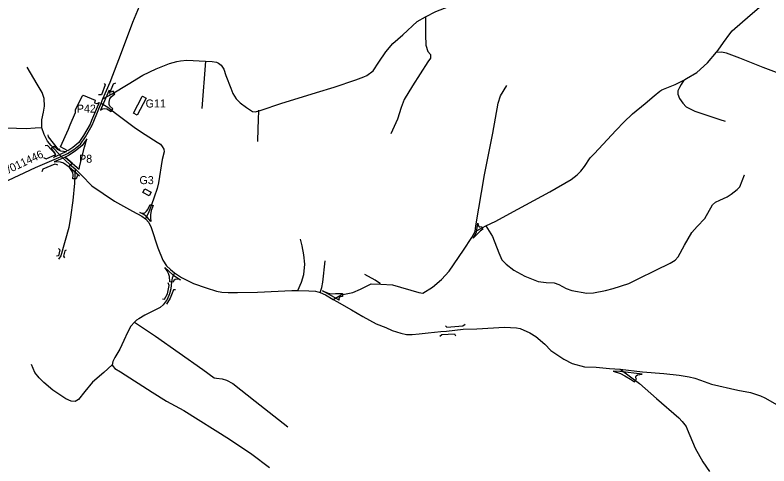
# Model space of a CAD drawing. Extents: x -439169 to -431590, y -1130011 to -1121081.
# Drawn here: x -437746 to -436804, y -1124342 to -1123779 of the extents above; entities that cross this region are included whole.
import ezdxf

# ---------------------------------------------------------------- set-up
doc = ezdxf.new("R2010")
doc.units = 0
for name, color, linetype in [('11811012_místní  komunikace_Stav', 7, 'Continuous'), ('11850012_silnice III třídy_Stav', 7, 'Continuous'), ('11850013_silnice III třídy_Stav', 7, 'Continuous'), ('11900012_účelová komunikace_Stav', 7, 'Continuous'), ('11930011_silniční most _ estakáda_Stav', 7, 'Continuous'), ('12060011_hromadná a parkovací garáž_Stav', 7, 'Continuous'), ('12060021_hromadná a parkovací garáž_Návrh', 7, 'Continuous'), ('12080011_parkoviště mimo prostor komunikace_Stav', 7, 'Continuous'), ('12080013_parkoviště mimo prostor komunikace_Stav', 7, 'Continuous')]:
    doc.layers.add(name, color=color, linetype=linetype)

msp = doc.modelspace()

# ---------------------------------------------------------------- linework, layer by layer
at = {"layer": '11811012_místní  komunikace_Stav'}
for points in [[(-437171.12, -1124049.48), (-437162.19, -1124044.79), (-437157.47, -1124042.33), (-437145.14, -1124036.37), (-437127.63, -1124026.96), (-437077.74, -1123999.89), (-437051.01, -1123984.4), (-437043.64, -1123978.68), (-437039.03, -1123973.89), (-437034.61, -1123967.99), (-437027.46, -1123957.15), (-437022.48, -1123952.17), (-436995.02, -1123922.48), (-436985.47, -1123912.78), (-436974.42, -1123902.09), (-436958.56, -1123889.36), (-436947.32, -1123879.96), (-436940.5, -1123874.06), (-436937.74, -1123872.4), (-436921.19, -1123865.6), (-436910.32, -1123860.06), (-436906.81, -1123858.22), (-436893.91, -1123850.48), (-436880.67, -1123838.52), (-436869.43, -1123825.25), (-436867.4, -1123822.67), (-436860.76, -1123813.08), (-436853.05, -1123802.26), (-436850.1, -1123798.39), (-436827.24, -1123778.84), (-436813.24, -1123766.85)], [(-437636.08, -1123883.43), (-437624.47, -1123877.16), (-437604.42, -1123865.04), (-437586.04, -1123853.98), (-437569.36, -1123846), (-437552.91, -1123839.49), (-437543.79, -1123836.77), (-437539.3, -1123835.94), (-437531.37, -1123835.35), (-437508.06, -1123836.58), (-437499.53, -1123836.99), (-437494.26, -1123837.72), (-437491.43, -1123838.91), (-437488.23, -1123841.38), (-437485.03, -1123846.32), (-437482.47, -1123854.55), (-437476.21, -1123870), (-437473.87, -1123876.86), (-437469.59, -1123883.52), (-437464.5, -1123888.37), (-437456.69, -1123894.29), (-437449.15, -1123899.27), (-437445.22, -1123899.82), (-437438.22, -1123897.84), (-437413.72, -1123889.36), (-437369.33, -1123875.54), (-437347.07, -1123868.9), (-437319.98, -1123859.87), (-437310.02, -1123855.81), (-437306.34, -1123854.15)], [(-437688.21, -1123955.73), (-437700.88, -1123941.89), (-437705.3, -1123936.47), (-437709.54, -1123927.99), (-437712.3, -1123919.69), (-437712.48, -1123909.6), (-437710.26, -1123900.01), (-437708.97, -1123892.64), (-437709.53, -1123883.23), (-437711.74, -1123875.67), (-437718, -1123864.98), (-437730.53, -1123843.82)], [(-437348.32, -1124134.23), (-437338.57, -1124128.5), (-437324.01, -1124125.78), (-437314.07, -1124121.28), (-437301.05, -1124114.77), (-437288.94, -1124115.39), (-437274.07, -1124116.08), (-437241.41, -1124125.78), (-437236.44, -1124126.37), (-437224.48, -1124119.04), (-437213.12, -1124109.45), (-437203.65, -1124099.05), (-437185.47, -1124072.77), (-437175.16, -1124056.77), (-437171.12, -1124049.48), (-437170.2, -1124042.28), (-437159.23, -1123978.37), (-437149.01, -1123926.54), (-437142.38, -1123888.8), (-437139.24, -1123879.95), (-437131.32, -1123866.86)], [(-437638.31, -1123889.08), (-437629.81, -1123894), (-437620.48, -1123901.62), (-437595.36, -1123920.11), (-437583.44, -1123928.26), (-437568.44, -1123937.51), (-437564.29, -1123940.21), (-437561.92, -1123942.95), (-437559.91, -1123946.61), (-437559.42, -1123949.57), (-437561.82, -1123959.52), (-437566.79, -1123988.6), (-437568.26, -1123995.43), (-437571.8, -1124006.63), (-437575.18, -1124016.15), (-437578.47, -1124024.65), (-437582.79, -1124033.49)], [(-437688.21, -1123955.73), (-437683.39, -1123960.36), (-437677.33, -1123965.51), (-437670.85, -1123971.05), (-437662.97, -1123979.06), (-437649.8, -1123992.14), (-437621.4, -1124011.29), (-437599.28, -1124024.01), (-437587.23, -1124030.39), (-437582.79, -1124033.49), (-437578.62, -1124038.31), (-437575.78, -1124044.37), (-437567.31, -1124069.59), (-437561.23, -1124085.08), (-437556.44, -1124092.28), (-437551.65, -1124096.7), (-437546.67, -1124101.13), (-437537.67, -1124106.97), (-437522.92, -1124114.35), (-437507.25, -1124119.69), (-437494.05, -1124124.08), (-437487.6, -1124125), (-437479.49, -1124125.56), (-437468.06, -1124125.56), (-437442.8, -1124125), (-437399.89, -1124123.16), (-437392.37, -1124123), (-437378.69, -1124123.34), (-437370.26, -1124124.08), (-437364.73, -1124125.56), (-437358.09, -1124128.69), (-437348.32, -1124134.23), (-437343.72, -1124136.7), (-437325.28, -1124147.13), (-437311.32, -1124155.58), (-437294.73, -1124164.8), (-437282.75, -1124169.41), (-437274.82, -1124173.1), (-437263.82, -1124176.59), (-437256.62, -1124178.06), (-437249.61, -1124178.06), (-437240.97, -1124177.14), (-437229.71, -1124176.03), (-437213.85, -1124174.19), (-437206.67, -1124173.82), (-437196.21, -1124172.53), (-437185.89, -1124171.42), (-437168.93, -1124170.87), (-437134.3, -1124168.86), (-437119.15, -1124169.81), (-437114.89, -1124170.75), (-437102.58, -1124176.2), (-437095.24, -1124180.7), (-437084.01, -1124190.23), (-437076.31, -1124197.98), (-437070.33, -1124202.35), (-437060.15, -1124208.92), (-437049.74, -1124214.37), (-437034.59, -1124218.63), (-437019.95, -1124218.75), (-437003, -1124220.41), (-436989.94, -1124221.51), (-436961.91, -1124224.61)], [(-437670.85, -1123971.05), (-437671.69, -1123988.91), (-437673.72, -1124010.67), (-437676.67, -1124031.32), (-437678.51, -1124044.23), (-437688.46, -1124079.59), (-437691.58, -1124084.14)], [(-437546.67, -1124101.13), (-437549.51, -1124107.62), (-437550.43, -1124112.41), (-437551.12, -1124121.03), (-437552.78, -1124127.11), (-437555.92, -1124134.49), (-437560.94, -1124140.9), (-437564.53, -1124144.22), (-437574.51, -1124149.25), (-437583.56, -1124153.82), (-437591.17, -1124158.33), (-437594.01, -1124160.26), (-437596.41, -1124162.84), (-437601.12, -1124167.87), (-437605.36, -1124175.62), (-437609.95, -1124185.41), (-437614.72, -1124196.42), (-437621.17, -1124206.94), (-437623.55, -1124211.85), (-437624.49, -1124215.97), (-437623.29, -1124218.11), (-437621.27, -1124220.51), (-437614.17, -1124224.64), (-437574.64, -1124250.28), (-437556.78, -1124261.32), (-437534.74, -1124273.15), (-437477.89, -1124309.12), (-437450.19, -1124327.53), (-437428.12, -1124344.34)], [(-436989.94, -1124221.51), (-436965.77, -1124239.3), (-436944.39, -1124257.92), (-436916.74, -1124282.08), (-436912.31, -1124286.88), (-436907.56, -1124293.26), (-436906.27, -1124296.4), (-436896.14, -1124320.18), (-436886.55, -1124337.33), (-436878.07, -1124349.51)], [(-436961.91, -1124224.61), (-436935.18, -1124226.92), (-436915.95, -1124229.12), (-436903.51, -1124231.15), (-436896.6, -1124232.63), (-436889.41, -1124235.03), (-436875.76, -1124240.4), (-436842.73, -1124247.63), (-436827.15, -1124250.77), (-436814.66, -1124254.63), (-436809.22, -1124257.21), (-436793.73, -1124265.97)]]:
    msp.add_lwpolyline(points, dxfattribs=at)
for points in [[(-437638.91, -1123897.76), (-437636.29, -1123896.06), (-437633.91, -1123895.45), (-437631.04, -1123895.93), (-437625.86, -1123899.16), (-437623.59, -1123895.86), (-437627.27, -1123892.58), (-437628.12, -1123890.63), (-437628.42, -1123887.58), (-437627.57, -1123883.37), (-437625.68, -1123881.06), (-437621.03, -1123877.42), (-437623.1, -1123874), (-437625.5, -1123874.84), (-437627.02, -1123875.02), (-437627.81, -1123874.84), (-437628.32, -1123872.65), (-437632.89, -1123883.01)], [(-437697.77, -1123956.81), (-437695.86, -1123955.02), (-437695.43, -1123953.56), (-437695.98, -1123951), (-437700.48, -1123945.28), (-437697.53, -1123942.58), (-437693.18, -1123946.43), (-437689.16, -1123948.68), (-437681.63, -1123949.53), (-437689.34, -1123953.23)], [(-437696.85, -1123962.39), (-437693.56, -1123962.01), (-437689.3, -1123962.13), (-437685.09, -1123963.48), (-437678.24, -1123968.68), (-437674.34, -1123964.12), (-437683.2, -1123956.38), (-437687.07, -1123958.24)], [(-437673.23, -1123978.95), (-437673.82, -1123975.73), (-437674.73, -1123973.66), (-437678.24, -1123968.68), (-437672.13, -1123973.9), (-437665.35, -1123979.57), (-437666.99, -1123979.51), (-437668.39, -1123980.24), (-437669.44, -1123983.59), (-437673.44, -1123983.46)], [(-437589.71, -1124025.77), (-437586.16, -1124026.6), (-437583.56, -1124025.89), (-437581.76, -1124024.1), (-437579.93, -1124021.9), (-437577.05, -1124015.45), (-437573.3, -1124016.84), (-437575.71, -1124023.05), (-437576.56, -1124028.61), (-437576.6, -1124031.94), (-437576.08, -1124036.66), (-437580.59, -1124031.45), (-437584.98, -1124028.26)], [(-437163.12, -1124043.02), (-437161.26, -1124046.56), (-437164.61, -1124048.84), (-437167.66, -1124051.72), (-437173.44, -1124057.8), (-437169.18, -1124050.11), (-437167.58, -1124039.01), (-437167.37, -1124041.85), (-437166.13, -1124043.38), (-437164.72, -1124043.5)], [(-437552.42, -1124112.14), (-437552.77, -1124105.72), (-437553.93, -1124101.69), (-437555.76, -1124098.43), (-437558.74, -1124094.24), (-437548.49, -1124103.52), (-437539.16, -1124109.58), (-437542.88, -1124108.76), (-437545.86, -1124109.48), (-437547.52, -1124110.75), (-437548.45, -1124112.68)], [(-437361.64, -1124123.67), (-437354.55, -1124126.53), (-437350.03, -1124127.18), (-437345.57, -1124126.88), (-437336.67, -1124126.73), (-437336.64, -1124130.73), (-437339.46, -1124131.23), (-437340.7, -1124132.17), (-437341.23, -1124133.64), (-437340.7, -1124135.39), (-437350.56, -1124129.81)], [(-436998.41, -1124223.81), (-436989.53, -1124226.66), (-436983.9, -1124229.65), (-436977.09, -1124233.88), (-436971.79, -1124237.35), (-436969.42, -1124234.13), (-436970.39, -1124232.47), (-436970.39, -1124230.94), (-436969.74, -1124229.65), (-436968.34, -1124228.59), (-436962.23, -1124227.6), (-436990.23, -1124224.5)]]:
    msp.add_lwpolyline(points, close=True, dxfattribs=at)
at = {"layer": '11850012_silnice III třídy_Stav'}
for points in [[(-437647.55, -1123911.51), (-437638.31, -1123889.08), (-437636.08, -1123883.43), (-437627, -1123862.82), (-437612.99, -1123825.77), (-437598.62, -1123787.61), (-437590.36, -1123767.65)], [(-437688.21, -1123955.73), (-437680.29, -1123951.94), (-437672.18, -1123946.78), (-437664.08, -1123940.15), (-437657.81, -1123930.93), (-437649.39, -1123916.3), (-437647.55, -1123911.51)], [(-437761, -1123988.44), (-437720.1, -1123969.27), (-437688.21, -1123955.73)]]:
    msp.add_lwpolyline(points, dxfattribs=at)
at = {"layer": '11900012_účelová komunikace_Stav'}
msp.add_line((-437507.76, -1123836.59), (-437512.49, -1123895.77), dxfattribs=at)
for points in [[(-437306.34, -1123854.15), (-437298.61, -1123848.5), (-437291.24, -1123837.81), (-437282.76, -1123824.9), (-437273.91, -1123814.2), (-437261.37, -1123803.5), (-437243.3, -1123786.9), (-437232.98, -1123781), (-437220.07, -1123774.36), (-437203.8, -1123767.95), (-437198.26, -1123765.82), (-437194.77, -1123764.82)], [(-437232.98, -1123781), (-437232.88, -1123803.53), (-437232.51, -1123816.44), (-437229.93, -1123824.19), (-437226.61, -1123828.24), (-437226.61, -1123832.67), (-437229.93, -1123837.47), (-437249.1, -1123867.34), (-437259.79, -1123884.31), (-437263.48, -1123894.27), (-437267.91, -1123909.03), (-437276.39, -1123927.47)], [(-436869.43, -1123825.25), (-436863.02, -1123824.83), (-436857.49, -1123825.84), (-436840.96, -1123832.45), (-436811.46, -1123843.89), (-436784.78, -1123854.1), (-436754.84, -1123865.06), (-436741.38, -1123870.96), (-436735.48, -1123874), (-436729.68, -1123876.86)], [(-436910.32, -1123860.06), (-436913.67, -1123865.62), (-436915.78, -1123869.42), (-436917.62, -1123873.48), (-436917.62, -1123877.72), (-436915.78, -1123883.25), (-436911.72, -1123888.78), (-436907.48, -1123893.39), (-436896.61, -1123898.74), (-436865.45, -1123909.25), (-436858.82, -1123911.47)], [(-437441.53, -1123897.56), (-437442.08, -1123910.29), (-437442.45, -1123920.43), (-437443.01, -1123936.84)], [(-437712.3, -1123919.69), (-437720.84, -1123920.04), (-437731.71, -1123920.96), (-437743.88, -1123920.78), (-437756.41, -1123920.04)], [(-437157.47, -1124042.33), (-437149.54, -1124055.42), (-437141.62, -1124076.08), (-437137.56, -1124084.74), (-437132.4, -1124090.09), (-437122.81, -1124097.65), (-437108.99, -1124105.4), (-437092.21, -1124111.85), (-437082.12, -1124112.94), (-437072.17, -1124113.68), (-437066.64, -1124115.71), (-437057.23, -1124120.5), (-437050.04, -1124123.08), (-437031.49, -1124126.37), (-437023.2, -1124125.82), (-437008.08, -1124123.24), (-436998.68, -1124120.66), (-436979.14, -1124114.39), (-436967.35, -1124108.67), (-436945.46, -1124097.82), (-436927.4, -1124088.79), (-436920.95, -1124085.1), (-436917.44, -1124080.86), (-436909.33, -1124066.48), (-436900.11, -1124050.62), (-436893.48, -1124043.05), (-436884.11, -1124033.14), (-436874.34, -1124015.99), (-436870.65, -1124012.67), (-436865.49, -1124010.09), (-436856.09, -1124005.84), (-436851.11, -1124002.53), (-436843.61, -1123996.9), (-436841.25, -1123994.56), (-436840.48, -1123993.39), (-436834.58, -1123978.64), (-436834.46, -1123978.34)], [(-437392.37, -1124123), (-437388.13, -1124112.75), (-437385.18, -1124102.98), (-437383.89, -1124090.07), (-437385.18, -1124078.45), (-437387.21, -1124067.2), (-437389.24, -1124059.09)], [(-437364.73, -1124125.56), (-437362.69, -1124119.5), (-437361.41, -1124112.56), (-437358.27, -1124085.83)], [(-437289.46, -1124114.54), (-437290.3, -1124113.98), (-437296.02, -1124110.1), (-437308.74, -1124103.1)], [(-437596.41, -1124162.84), (-437570.32, -1124180), (-437511.18, -1124221.83), (-437497.17, -1124232.35), (-437494.04, -1124232.9), (-437487.03, -1124233.64), (-437481.73, -1124235.09), (-437473.62, -1124239.52), (-437445.78, -1124261.28), (-437405.08, -1124293.51)], [(-437624.49, -1124215.97), (-437634.87, -1124225.77), (-437648.88, -1124237.76), (-437658.44, -1124249.34), (-437666.73, -1124259.49), (-437670.79, -1124261.7), (-437675.77, -1124261.33), (-437682.22, -1124258.38), (-437698.44, -1124247.87), (-437710.02, -1124238.11), (-437715.73, -1124232.4), (-437721.08, -1124225.57), (-437725.14, -1124215.43)]]:
    msp.add_lwpolyline(points, dxfattribs=at)
at = {"layer": '11930011_silniční most _ estakáda_Stav'}
for points in [[(-437634.54, -1123864.15), (-437633.07, -1123865.99), (-437637.86, -1123878.35), (-437641.37, -1123878.72)], [(-437620.35, -1123863.78), (-437623.11, -1123865.07), (-437627.91, -1123876.51), (-437627.17, -1123878.35)], [(-437704.74, -1123928.42), (-437704.56, -1123931), (-437691.84, -1123946.68), (-437689.44, -1123946.13)], [(-437710.38, -1123956.88), (-437706.88, -1123958.72), (-437694.71, -1123953.01), (-437705.11, -1123941.89), (-437708.06, -1123942.44)], [(-437711.94, -1123974.35), (-437710.65, -1123971.03), (-437695.89, -1123964.57), (-437692.76, -1123965.86)], [(-437691.37, -1124070.66), (-437689.8, -1124072.32), (-437691.65, -1124079.61), (-437694.04, -1124080.07)], [(-437682.15, -1124072.6), (-437683.72, -1124073.43), (-437685.38, -1124080.35), (-437683.99, -1124082.47)], [(-437561.58, -1124133.6), (-437559.27, -1124133.78), (-437555.4, -1124127.42), (-437553.1, -1124116.81), (-437554.57, -1124113.68)], [(-437545.26, -1124122.44), (-437548.03, -1124122.16), (-437552.08, -1124132.58), (-437556.69, -1124140.24)], [(-437208.17, -1124167.25), (-437206.23, -1124169.1), (-437186.24, -1124167.44), (-437183.29, -1124165.32)], [(-437215.23, -1124180.3), (-437212.59, -1124178.04), (-437197.01, -1124177.21), (-437195.44, -1124179.61)]]:
    msp.add_lwpolyline(points, dxfattribs=at)
at = {"layer": '12060011_hromadná a parkovací garáž_Stav'}
for points in [[(-437586.74, -1123880.25), (-437582.01, -1123882.59), (-437593.2, -1123903.82), (-437597.86, -1123901.36), (-437586.96, -1123880.66)], [(-437583.48, -1123995.94), (-437575.64, -1124000.37), (-437578.24, -1124004.96), (-437586.07, -1124000.53)]]:
    msp.add_lwpolyline(points, close=True, dxfattribs=at)
at = {"layer": '12080011_parkoviště mimo prostor komunikace_Stav'}
for points in [[(-437679.86, -1123948.41), (-437688.89, -1123943.4), (-437679.19, -1123921.27), (-437676.82, -1123915.83), (-437670.17, -1123900.62), (-437670.31, -1123897.01), (-437661.55, -1123879.73), (-437660.6, -1123879.02), (-437645.57, -1123885.06), (-437646.64, -1123888.37), (-437643.58, -1123889.26), (-437642.3, -1123888.84), (-437640.86, -1123888.05), (-437650.09, -1123910.46), (-437651.88, -1123915.1), (-437660.14, -1123929.47), (-437666.13, -1123938.27), (-437673.8, -1123944.55)], [(-437683.2, -1123956.38), (-437668.28, -1123969.29), (-437665.57, -1123971.56), (-437664.72, -1123966.72), (-437659.02, -1123944.03), (-437656.15, -1123933.37), (-437662.03, -1123942.02), (-437670.57, -1123949.01), (-437678.96, -1123954.35)]]:
    msp.add_lwpolyline(points, close=True, dxfattribs=at)

# ---------------------------------------------------------------- texts
at = {"layer": '11850013_silnice III třídy_Stav'}
msp.add_text('III/011446', height=10, rotation=25.1695, dxfattribs=at).set_placement((-437763.17, -1123981.44))
at = {"layer": '12060021_hromadná a parkovací garáž_Návrh'}
for s, p in [('G11', (-437582.71, -1123894.35)), ('G3', (-437590.39, -1123990.13))]:
    msp.add_text(s, height=10, dxfattribs=at).set_placement(p)
at = {"layer": '12080013_parkoviště mimo prostor komunikace_Stav'}
for s, p in [('P42', (-437668.68, -1123900.77)), ('P8', (-437665.81, -1123963.4))]:
    msp.add_text(s, height=10, dxfattribs=at).set_placement(p)

doc.saveas('drawing.dxf')
